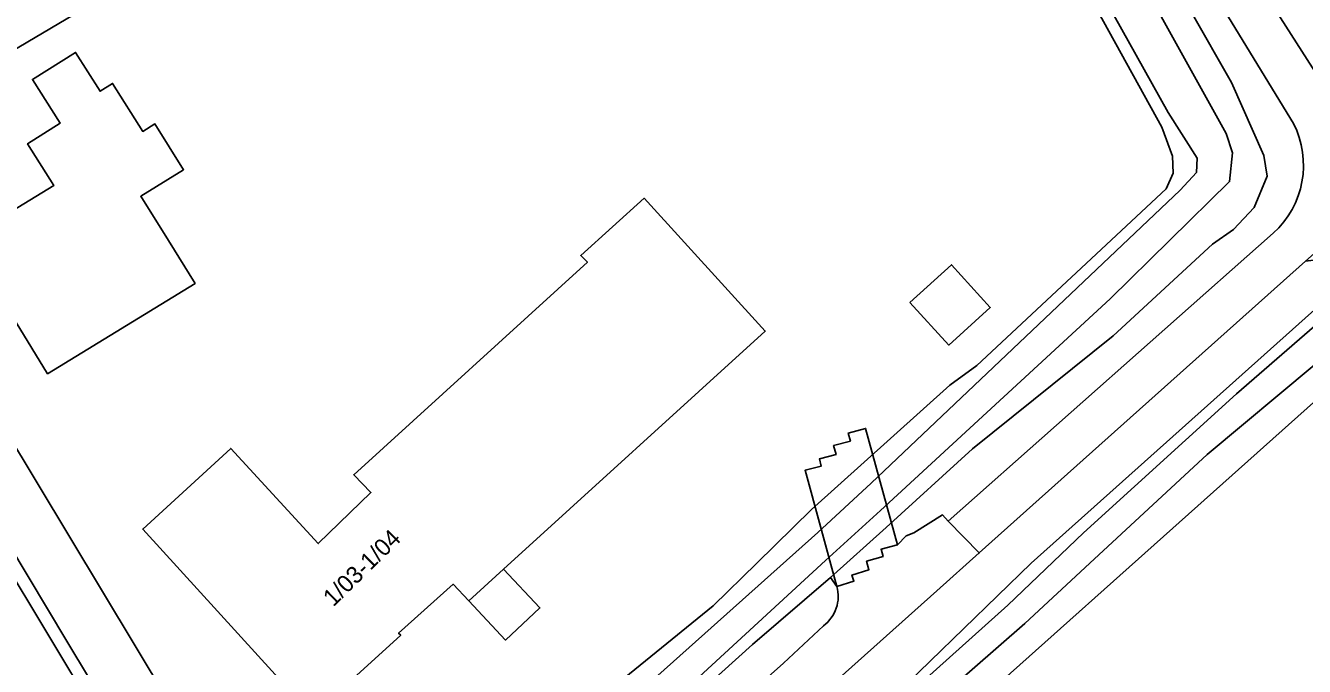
# Model space of a CAD drawing. Extents: x 162788 to 163838, y 385791 to 386523.
# Drawn here: x 163321.5 to 163396.5, y 386243.9 to 386281.5 of the extents above; entities that cross this region are included whole.
import ezdxf

# ---------------------------------------------------------------- set-up
doc = ezdxf.new("R2010")
doc.units = 0
for name, color, linetype in [('IMGEO_Dek', 7, 'Continuous'), ('IMGEO_Erf', 7, 'Continuous'), ('IMGEO_Gemengd_bos', 7, 'Continuous'), ('IMGEO_Groenvoorziening', 7, 'Continuous'), ('IMGEO_Oever', 7, 'Continuous'), ('IMGEO_Pand', 7, 'Continuous'), ('IMGEO_Pand_nummerreeks', 7, 'Continuous'), ('IMGEO_Rijbaan_lokaal_gesloten', 7, 'Continuous'), ('IMGEO_Rijbaan_lokaal_open', 7, 'Continuous'), ('IMGEO_Voetpad_halfverhard', 7, 'Continuous'), ('IMGEO_Voetpad_open', 7, 'Continuous'), ('IMGEO_Waterloop', 7, 'Continuous')]:
    doc.layers.add(name, color=color, linetype=linetype)

msp = doc.modelspace()

# ---------------------------------------------------------------- linework, layer by layer
at = {"layer": 'IMGEO_Dek'}
msp.add_lwpolyline([(163372.634, 386251.069), (163370.763, 386257.897), (163369.751, 386257.631), (163369.876, 386257.156), (163368.895, 386256.898), (163369.034, 386256.368), (163368.058, 386256.112), (163368.168, 386255.693), (163367.216, 386255.443), (163369.085, 386248.634), (163370.079, 386248.938), (163370.023, 386249.117), (163369.965, 386249.304), (163370.962, 386249.615), (163370.823, 386250.113), (163371.791, 386250.393), (163371.734, 386250.605), (163371.678, 386250.815)], close=True, dxfattribs=at)
at = {"layer": 'IMGEO_Erf'}
msp.add_lwpolyline([(163353.891, 386241.041), (163361.83, 386247.495), (163364.388, 386250), (163367.592, 386253.137), (163370.682, 386255.929), (163375.708, 386260.443), (163377.288, 386261.582), (163388.388, 386271.954), (163388.788, 386272.873), (163388.748, 386273.873), (163388.129, 386275.573), (163369.598, 386309.184), (163358.272, 386329.726), (163357.191, 386329.246), (163367.738, 386310.106), (163368.442, 386308.828), (163368.586, 386308.579), (163331.921, 386286.666), (163328.501, 386284.648), (163313.313, 386275.651), (163310.566, 386274.054), (163311.675, 386272.212), (163320.288, 386257.903), (163335.62, 386232.403)], dxfattribs=at)
for points in [[(163331.468, 386266.404), (163322.825, 386261.107), (163317.999, 386268.982), (163323.193, 386272.15), (163321.652, 386274.6), (163323.552, 386275.796), (163321.936, 386278.366), (163324.464, 386279.955), (163325.896, 386277.677), (163326.626, 386278.135), (163328.395, 386275.322), (163329.109, 386275.758), (163330.796, 386273.076), (163328.286, 386271.513), (163329.901, 386268.92)], [(163357.784, 386271.398), (163364.885, 386263.612), (163349.547, 386249.655), (163351.682, 386247.374), (163349.665, 386245.486), (163347.503, 386247.795), (163346.594, 386248.766), (163343.394, 386245.892), (163343.524, 386245.771), (163338.348, 386241.072), (163328.399, 386252.001), (163333.557, 386256.725), (163338.682, 386251.144), (163341.775, 386254.136), (163340.766, 386255.179), (163354.467, 386267.645), (163354.072, 386268.035)], [(163373.363, 386265.291), (163375.794, 386267.502), (163378.075, 386264.995), (163375.644, 386262.784)]]:
    msp.add_lwpolyline(points, close=True, dxfattribs=at)
at = {"layer": 'IMGEO_Gemengd_bos'}
msp.add_lwpolyline([(163280.535, 386245.437), (163281.575, 386245.437), (163287.173, 386237.078), (163293.429, 386226.72), (163294.292, 386224.795), (163295.345, 386224.545), (163299.832, 386224.953), (163303.289, 386225.225), (163304.457, 386225.417), (163306.785, 386226.045), (163314.356, 386228.407), (163317.791, 386229.476), (163319.029, 386229.803), (163320.384, 386230.073), (163323.553, 386230.6), (163331.222, 386231.885), (163311.632, 386264.441)], dxfattribs=at)
at = {"layer": 'IMGEO_Groenvoorziening'}
for points in [[(163366.85, 386330.883), (163369.907, 386325.103), (163374.484, 386317.043), (163382.178, 386304.225), (163394.769, 386282.467), (163399.006, 386275.848), (163399.486, 386275.328), (163400.186, 386275.048), (163400.745, 386275.007), (163401.845, 386275.387), (163405.006, 386278.384), (163406.486, 386281.822), (163413.59, 386302.652), (163418.494, 386319.105), (163419.455, 386323.463), (163419.315, 386323.943), (163418.655, 386324.563), (163414.456, 386326.584), (163407.799, 386328.806), (163374.311, 386338.917)], [(163395.847, 386275.789), (163391.61, 386282.729), (163364.835, 386329.753)], [(163380.397, 386298.927), (163392.208, 386278.19), (163394.108, 386273.91), (163394.307, 386272.691), (163393.547, 386270.852), (163392.327, 386269.573), (163391.107, 386268.713), (163385.287, 386263.338), (163377.028, 386256.705), (163371.965, 386252.091), (163368.701, 386249.163), (163369.085, 386248.634), (163370.079, 386248.938), (163370.023, 386249.117), (163369.965, 386249.304), (163370.962, 386249.615), (163370.823, 386250.113), (163371.791, 386250.393), (163371.734, 386250.605), (163371.678, 386250.815), (163372.634, 386251.069), (163373.138, 386251.611), (163373.589, 386251.779), (163375.266, 386252.833), (163375.617, 386252.47), (163394.666, 386269.352)], [(163429.756, 386214.729), (163399.737, 386267.865), (163397.828, 386267.865), (163396.545, 386267.701), (163396.181, 386267.38), (163382.605, 386255.233), (163377.425, 386250.598), (163374.942, 386248.377), (163355.394, 386230.887)], [(163311.632, 386264.441), (163331.222, 386231.885), (163332.017, 386232.018), (163331.635, 386232.654), (163323.947, 386245.43), (163319.391, 386253.017), (163311.237, 386266.337)], [(163372.586, 386242.333), (163380.464, 386250), (163397.824, 386265.512), (163398.663, 386265.651), (163399.364, 386265.332), (163400.463, 386264.272), (163401.443, 386263.032), (163403.381, 386259.812), (163404.56, 386257.293), (163408.847, 386250), (163410.376, 386246.794), (163411.856, 386244.174), (163413.194, 386241.854)], [(163369.085, 386248.634), (163368.701, 386249.163), (163364.148, 386245.235), (163356.55, 386238.382)], [(163353.626, 386233.163), (163365.956, 386244.126), (163368.299, 386246.329)]]:
    msp.add_lwpolyline(points, dxfattribs=at)
msp.add_lwpolyline([(163414.752, 386232.441), (163403.009, 386252.5), (163398.124, 386260.392), (163369.367, 386234.714), (163371.151, 386232.712), (163374.704, 386235.794), (163375.63, 386234.852), (163337.575, 386201.193), (163348.928, 386182.754), (163362.099, 386162.584), (163427.28, 386208.259)], close=True, dxfattribs=at)
for centre, radius, start, end in [((163391.038, 386273.345), 5.395, 312.26445, 26.94262), ((163366.996, 386248.06), 2.167, 306.97948, 15.36199)]:
    msp.add_arc(centre, radius, start, end, dxfattribs=at)
at = {"layer": 'IMGEO_Oever'}
for points in [[(163342.033, 386228.609), (163367.964, 386251.803), (163371.098, 386254.685), (163389.207, 386271.878), (163390.16, 386272.907), (163390.211, 386273.755), (163388.512, 386276.431), (163379.782, 386292.073), (163359.432, 386330.246), (163358.272, 386329.726), (163369.598, 386309.184), (163388.129, 386275.573), (163388.748, 386273.873), (163388.788, 386272.873), (163388.388, 386271.954), (163377.288, 386261.582), (163375.708, 386260.443), (163370.682, 386255.929), (163367.592, 386253.137), (163364.388, 386250), (163361.83, 386247.495), (163353.891, 386241.041)], [(163356.55, 386238.382), (163364.148, 386245.235), (163368.701, 386249.163), (163371.965, 386252.091), (163377.028, 386256.705), (163385.287, 386263.338), (163391.107, 386268.713), (163392.327, 386269.573), (163393.547, 386270.852), (163394.307, 386272.691), (163394.108, 386273.91), (163392.208, 386278.19), (163380.397, 386298.927)], [(163384.063, 386289.338), (163391.897, 386275.192), (163392.27, 386274.061), (163392.105, 386272.373), (163385.103, 386265.501), (163371.634, 386253.081), (163368.424, 386250.152), (163343.262, 386226.971)], [(163413.194, 386241.854), (163411.856, 386244.174), (163410.376, 386246.794), (163408.847, 386250), (163404.56, 386257.293), (163403.381, 386259.812), (163401.443, 386263.032), (163400.463, 386264.272), (163399.364, 386265.332), (163398.663, 386265.651), (163397.824, 386265.512), (163380.464, 386250), (163372.586, 386242.333)], [(163367.324, 386236.953), (163379.098, 386247.54), (163383.536, 386251.787), (163392.508, 386259.928), (163397.814, 386264.534), (163398.063, 386264.716), (163398.312, 386264.839), (163398.653, 386264.891), (163398.974, 386264.845), (163399.357, 386264.639), (163399.483, 386264.501), (163399.649, 386264.24), (163406.837, 386251.618), (163419.995, 386228.198)], [(163397.066, 386261.62), (163390.784, 386256.379), (163383.911, 386250), (163380.105, 386246.467), (163370.686, 386238.235)], [(163369.367, 386234.714), (163398.124, 386260.392), (163403.009, 386252.5), (163414.752, 386232.441)]]:
    msp.add_lwpolyline(points, dxfattribs=at)
at = {"layer": 'IMGEO_Pand'}
for points in [[(163329.901, 386268.92), (163328.286, 386271.513), (163330.796, 386273.076), (163329.109, 386275.758), (163328.395, 386275.322), (163326.626, 386278.135), (163325.896, 386277.677), (163324.464, 386279.955), (163321.936, 386278.366), (163323.552, 386275.796), (163321.652, 386274.6), (163323.193, 386272.15), (163317.999, 386268.982), (163322.825, 386261.107), (163331.468, 386266.404)], [(163364.885, 386263.612), (163357.784, 386271.398), (163354.072, 386268.035), (163354.467, 386267.645), (163340.766, 386255.179), (163341.775, 386254.136), (163338.682, 386251.144), (163333.557, 386256.725), (163328.399, 386252.001), (163338.348, 386241.072), (163343.524, 386245.771), (163343.394, 386245.892), (163346.594, 386248.766), (163347.503, 386247.795), (163349.547, 386249.655)], [(163373.363, 386265.291), (163375.644, 386262.784), (163378.075, 386264.995), (163375.794, 386267.502)], [(163349.547, 386249.655), (163347.503, 386247.795), (163349.665, 386245.486), (163351.682, 386247.374)]]:
    msp.add_lwpolyline(points, close=True, dxfattribs=at)
at = {"layer": 'IMGEO_Rijbaan_lokaal_gesloten'}
for points in [[(163374.942, 386248.377), (163377.425, 386250.598), (163375.617, 386252.47), (163375.266, 386252.833), (163373.589, 386251.779), (163373.138, 386251.611), (163372.634, 386251.069), (163371.678, 386250.815), (163371.734, 386250.605), (163371.791, 386250.393), (163370.823, 386250.113), (163370.962, 386249.615), (163369.965, 386249.304), (163370.023, 386249.117), (163370.079, 386248.938), (163369.085, 386248.634)], [(163368.299, 386246.329), (163365.956, 386244.126), (163353.626, 386233.163), (163345.451, 386225.733), (163344.351, 386224.614), (163343.508, 386223.983), (163343.393, 386223.87), (163343.339, 386223.825), (163345.194, 386221.761), (163355.394, 386230.887), (163374.942, 386248.377)]]:
    msp.add_lwpolyline(points, dxfattribs=at)
msp.add_arc((163366.996, 386248.06), 2.167, 306.97948, 15.36199, dxfattribs=at)
at = {"layer": 'IMGEO_Rijbaan_lokaal_open'}
for points in [[(163311.237, 386266.337), (163319.391, 386253.017), (163323.947, 386245.43), (163331.635, 386232.654)], [(163335.62, 386232.403), (163320.288, 386257.903)]]:
    msp.add_lwpolyline(points, dxfattribs=at)
at = {"layer": 'IMGEO_Voetpad_halfverhard'}
for points in [[(163313.313, 386275.651), (163328.501, 386284.648), (163331.921, 386286.666), (163368.586, 386308.579), (163368.442, 386308.828), (163367.738, 386310.106), (163357.191, 386329.246), (163356.332, 386330.786), (163344.708, 386351.209), (163342.163, 386350.128), (163326.785, 386344.429), (163326.437, 386345.367), (163323.577, 386344.307), (163323.925, 386343.37), (163308.379, 386337.609)], [(163394.666, 386269.352), (163375.617, 386252.47), (163377.425, 386250.598), (163382.605, 386255.233), (163396.181, 386267.38), (163396.545, 386267.701), (163401.635, 386272.202), (163399.006, 386275.848), (163394.769, 386282.467), (163382.178, 386304.225), (163374.484, 386317.043), (163369.907, 386325.103), (163366.85, 386330.883), (163358.189, 386346.172), (163358.156, 386346.279)], [(163360.332, 386332.605), (163357.392, 386331.246), (163356.332, 386330.786), (163357.191, 386329.246), (163358.272, 386329.726), (163359.432, 386330.246), (163360.824, 386330.87), (163362.853, 386330.804), (163363.52, 386330.763), (163364.151, 386330.543), (163364.835, 386329.753), (163391.61, 386282.729), (163395.847, 386275.789)]]:
    msp.add_lwpolyline(points, dxfattribs=at)
msp.add_arc((163391.038, 386273.345), 5.395, 312.26445, 26.94262, dxfattribs=at)
at = {"layer": 'IMGEO_Voetpad_open'}
msp.add_lwpolyline([(163372.634, 386251.069), (163370.763, 386257.897), (163369.751, 386257.631), (163369.876, 386257.156), (163368.895, 386256.898), (163369.034, 386256.368), (163368.058, 386256.112), (163368.168, 386255.693), (163367.216, 386255.443), (163369.085, 386248.634), (163370.079, 386248.938), (163370.023, 386249.117), (163369.965, 386249.304), (163370.962, 386249.615), (163370.823, 386250.113), (163371.791, 386250.393), (163371.734, 386250.605), (163371.678, 386250.815)], close=True, dxfattribs=at)
at = {"layer": 'IMGEO_Waterloop'}
for points in [[(163343.262, 386226.971), (163368.424, 386250.152), (163371.634, 386253.081), (163385.103, 386265.501), (163392.105, 386272.373), (163392.27, 386274.061), (163391.897, 386275.192), (163384.063, 386289.338), (163374.749, 386305.83), (163366.127, 386321.619), (163360.824, 386330.87), (163359.432, 386330.246), (163379.782, 386292.073), (163388.512, 386276.431), (163390.211, 386273.755), (163390.16, 386272.907), (163389.207, 386271.878), (163371.098, 386254.685), (163367.964, 386251.803), (163342.033, 386228.609)], [(163419.995, 386228.198), (163406.837, 386251.618), (163399.649, 386264.24), (163399.483, 386264.501), (163399.357, 386264.639), (163398.974, 386264.845), (163398.653, 386264.891), (163398.312, 386264.839), (163398.063, 386264.716), (163397.814, 386264.534), (163392.508, 386259.928), (163383.536, 386251.787), (163379.098, 386247.54), (163367.324, 386236.953)], [(163370.686, 386238.235), (163380.105, 386246.467), (163383.911, 386250), (163390.784, 386256.379), (163397.066, 386261.62), (163398.596, 386261.532), (163401.973, 386255.975), (163407.495, 386247.322), (163423.095, 386219.402)]]:
    msp.add_lwpolyline(points, dxfattribs=at)

# ---------------------------------------------------------------- texts
at = {"layer": 'IMGEO_Pand_nummerreeks'}
msp.add_text('1/03-1/04', height=1, rotation=44.38704, dxfattribs=at).set_placement((163339.564, 386247.405))

doc.saveas('drawing.dxf')
